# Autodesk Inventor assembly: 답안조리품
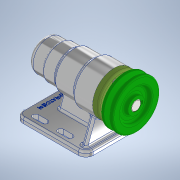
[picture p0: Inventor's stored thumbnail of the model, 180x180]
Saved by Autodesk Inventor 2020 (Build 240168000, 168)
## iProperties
Created: 2021-10
Part Number: 답안조리품
Document SubType Name: Assembly
Designer: user
Author: user
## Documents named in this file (12)
- C:\Users\user\Desktop\711007V1018\답안조리품.iam
- C:\Users\user\Desktop\711007V1018\V벨트풀리.ipt
- C:\Users\user\Desktop\711007V1018\멈춤나사 M3.ipt
- C:\Users\user\Desktop\711007V1018\베어링 6004.ipt
- C:\Users\user\Desktop\711007V1018\베어링 51202.ipt
- C:\Users\user\Desktop\711007V1018\본체.ipt
- C:\Users\user\Desktop\711007V1018\볼트 M4.ipt
- C:\Users\user\Desktop\711007V1018\어댑터슬리브.ipt
- C:\Users\user\Desktop\711007V1018\오일 실 20x35x7.ipt
- C:\Users\user\Desktop\711007V1018\축.ipt
- C:\Users\user\Desktop\711007V1018\커버.ipt
- C:\Users\user\Desktop\711007V1018\키 5x5.ipt
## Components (1 placed, 1 different names)
1. V벨트풀리:1
